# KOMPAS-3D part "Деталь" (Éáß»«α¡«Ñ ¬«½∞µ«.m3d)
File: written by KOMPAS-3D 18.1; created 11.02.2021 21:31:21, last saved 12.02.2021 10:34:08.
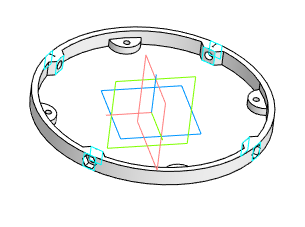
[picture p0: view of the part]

Document properties: Полное имя файла: C:\GoogleDrive\НИР\ИКИ\Компас\Распорное кольцо.m3d

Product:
- Part/product: Деталь
    Материал: Полипропилен  ГОСТ 26996-86 (density 900 kg/m3)
    Масса: 0.0192571

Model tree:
1. Эскиз:1
2. Элемент выдавливания:3
     Расстояние 1 = 10
3. Эскиз:2  (with: Элемент выдавливания:3)
4. Элемент выдавливания:4
     Расстояние 2 = 5
5. Плоскость через три точки:1  (with: Элемент выдавливания:3)
6. Плоскость через три точки:2  (with: Элемент выдавливания:3)
7. Плоскость через три точки:3  (with: Элемент выдавливания:3)
8. Плоскость через три точки:4  (with: Элемент выдавливания:3)
9. Отверстие:4
     Глубина выреза = 39.7811; Диаметр отверстия = 5.5; Угол конуса дна = 118; Расстояние 1 = -5; Расстояние 2 = 46.5776
10. Отверстие:5
     Глубина выреза = 171.523; Диаметр отверстия = 5.5; Угол конуса дна = 118; Расстояние 1 = -5; Расстояние 2 = -46.5776
11. Отверстие:6
     Глубина выреза = 39.7811; Диаметр отверстия = 5.5; Угол конуса дна = 118; Расстояние 1 = -5; Расстояние 2 = -46.5776
12. Отверстие:7
     Глубина выреза = 39.7811; Диаметр отверстия = 5.5; Угол конуса дна = 118; Расстояние 1 = -5; Расстояние 2 = -46.5776
13. Эскиз:3  (with: Элемент выдавливания:4)
14. Эскиз:4  (with: Элемент выдавливания:4)
15. Эскиз:5  (with: Элемент выдавливания:4)
16. Эскиз:6  (with: Элемент выдавливания:4)
17. Элемент выдавливания:5
     Расстояние 2 = 10
18. Элемент выдавливания:6
     Расстояние 2 = 10
19. Элемент выдавливания:7
     Расстояние 2 = 10
20. Элемент выдавливания:8
     Расстояние 2 = 10
21. Смещенная плоскость:1
     Расстояние = 8
22. Смещенная плоскость:2
     Расстояние = 8
23. Смещенная плоскость:3
     Расстояние = 8
24. Смещенная плоскость:4
     Расстояние = 8
25. Эскиз:8  (with: Элемент выдавливания:3)
26. Элемент выдавливания:10
     Расстояние 1 = 1; Расстояние 2 = 4
27. Эскиз:9  (with: Элемент выдавливания:3)
28. Элемент выдавливания:11
     Расстояние 1 = 1; Расстояние 2 = 4
29. Эскиз:10  (with: Элемент выдавливания:3)
30. Элемент выдавливания:12
     Расстояние 1 = 1; Расстояние 2 = 4
31. Эскиз:11  (with: Элемент выдавливания:3)
32. Элемент выдавливания:13  (labels: Полипропилен  ГОСТ 26996-86)
     Расстояние 1 = 1; Расстояние 2 = 4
